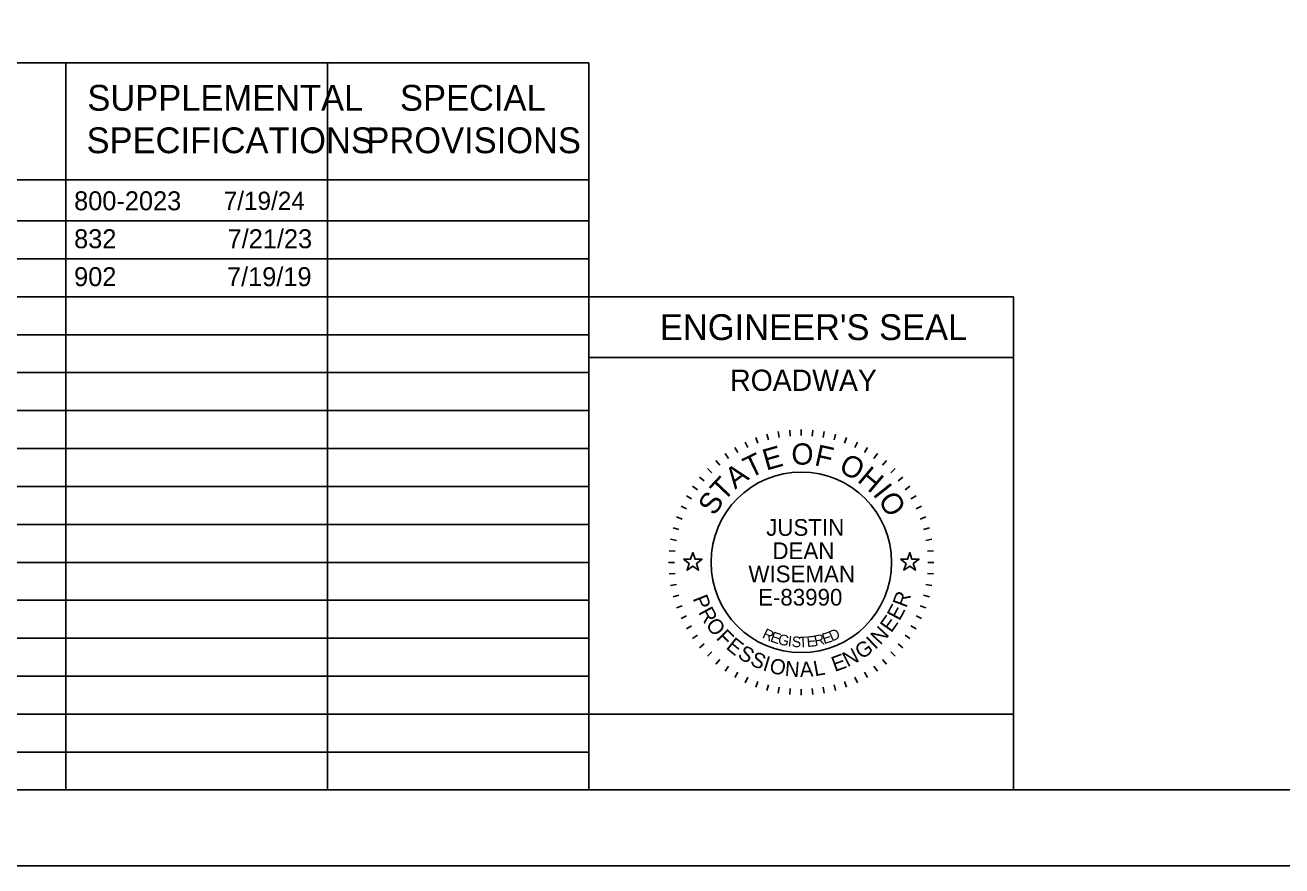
# Model space of a CAD drawing. Extents: x 0 to 34, y 0 to 22.
# Drawn here: x 19.88 to 28.17, y 0 to 5.54 of the extents above; entities that cross this region are included whole.
import ezdxf

# ---------------------------------------------------------------- set-up
doc = ezdxf.new("R2010")
doc.units = 0
for name, color, linetype in [('Default', 7, 'Continuous'), ('SH_Border', 7, 'Continuous'), ('SH_Cut_Line', 7, 'Continuous'), ('SH_Data', 7, 'Continuous'), ('SH_Text', 7, 'Continuous')]:
    doc.layers.add(name, color=color, linetype=linetype)

msp = doc.modelspace()

# ---------------------------------------------------------------- linework, layer by layer
at = {"layer": 'Default'}
for points in [[(24.2236, 2.02), (24.2705, 2.02), (24.285, 2.0645), (24.2995, 2.02), (24.3464, 2.02), (24.3085, 1.9924), (24.323, 1.9478), (24.285, 1.9754), (24.247, 1.9478), (24.2615, 1.9924)], [(25.6536, 2.02), (25.7005, 2.02), (25.715, 2.0645), (25.7295, 2.02), (25.7764, 2.02), (25.7385, 1.9924), (25.753, 1.9478), (25.715, 1.9754), (25.677, 1.9478), (25.6915, 1.9924)]]:
    msp.add_lwpolyline(points, close=True, dxfattribs=at)
at = {"layer": 'SH_Border'}
msp.add_lwpolyline([(1.5, 21.5), (33.5, 21.5), (33.5, 0.5), (1.5, 0.5)], close=True, dxfattribs=at)
at = {"layer": 'SH_Cut_Line'}
msp.add_lwpolyline([(0, 0), (34, 0), (34, 22), (0, 22)], close=True, dxfattribs=at)
at = {"layer": 'SH_Data'}
for p, q in [((10.15, 5.2917), (23.6, 5.2917)), ((20.15, 0.5), (20.15, 5.2917)), ((21.875, 0.5), (21.875, 5.2917)), ((23.6, 0.5), (23.6, 5.2917)), ((10.15, 4.5209), (23.6, 4.5209)), ((10.15, 4.25), (23.6, 4.25)), ((10.15, 4), (23.6, 4)), ((10.15, 3.75), (23.6, 3.75)), ((23.6, 0.5), (23.6, 3.75)), ((23.6, 3.75), (26.4, 3.75)), ((26.4, 3.75), (26.4, 0.5)), ((10.15, 3.5), (23.6, 3.5)), ((23.6, 3.35), (26.4, 3.35)), ((10.15, 3.25), (23.6, 3.25)), ((10.15, 3), (23.6, 3)), ((24.7007, 2.8222), (24.7144, 2.7846)), ((24.7735, 2.8452), (24.7839, 2.8065)), ((24.8481, 2.8617), (24.855, 2.8223)), ((24.9237, 2.8717), (24.9272, 2.8318)), ((25, 2.875), (25, 2.835)), ((25.0763, 2.8717), (25.0728, 2.8318)), ((25.1519, 2.8617), (25.145, 2.8223)), ((25.2265, 2.8452), (25.2161, 2.8065)), ((25.2993, 2.8222), (25.2856, 2.7846)), ((10.15, 2.75), (23.6, 2.75)), ((24.5625, 2.7578), (24.5825, 2.7231)), ((24.6302, 2.793), (24.6471, 2.7568)), ((25.3698, 2.793), (25.3529, 2.7568)), ((25.4375, 2.7578), (25.4175, 2.7231)), ((24.4376, 2.6703), (24.4633, 2.6396)), ((24.4981, 2.7168), (24.5211, 2.684)), ((25.5019, 2.7168), (25.4789, 2.684)), ((25.5624, 2.6703), (25.5367, 2.6396)), ((24.3813, 2.6187), (24.4096, 2.5904)), ((25.6187, 2.6187), (25.5904, 2.5904)), ((10.15, 2.5), (23.6, 2.5)), ((24.2832, 2.5019), (24.316, 2.4789)), ((24.3297, 2.5624), (24.3604, 2.5367)), ((25.6703, 2.5624), (25.6396, 2.5367)), ((25.7168, 2.5019), (25.684, 2.4789)), ((24.2422, 2.4375), (24.2769, 2.4175)), ((25.7578, 2.4375), (25.7231, 2.4175)), ((24.207, 2.3698), (24.2432, 2.3529)), ((25.793, 2.3698), (25.7568, 2.3529)), ((10.15, 2.25), (23.6, 2.25)), ((24.1778, 2.2993), (24.2154, 2.2856)), ((25.8222, 2.2993), (25.7846, 2.2856)), ((24.1548, 2.2265), (24.1935, 2.2161)), ((25.8452, 2.2265), (25.8065, 2.2161)), ((24.1283, 2.0763), (24.1682, 2.0728)), ((24.1383, 2.1519), (24.1777, 2.145)), ((25.8617, 2.1519), (25.8223, 2.145)), ((25.8717, 2.0763), (25.8318, 2.0728)), ((10.15, 2), (23.6, 2)), ((24.125, 2), (24.165, 2)), ((25.875, 2), (25.835, 2)), ((24.1283, 1.9237), (24.1682, 1.9272)), ((25.8717, 1.9237), (25.8318, 1.9272)), ((24.1383, 1.8481), (24.1777, 1.855)), ((25.8617, 1.8481), (25.8223, 1.855)), ((10.15, 1.75), (23.6, 1.75)), ((24.1548, 1.7735), (24.1935, 1.7839)), ((25.8452, 1.7735), (25.8065, 1.7839)), ((24.1778, 1.7007), (24.2154, 1.7144)), ((25.8222, 1.7007), (25.7846, 1.7144)), ((24.207, 1.6302), (24.2432, 1.6471)), ((24.2422, 1.5625), (24.2769, 1.5825)), ((25.7578, 1.5625), (25.7231, 1.5825)), ((25.793, 1.6302), (25.7568, 1.6471)), ((10.15, 1.5), (23.6, 1.5)), ((24.2832, 1.4981), (24.316, 1.5211)), ((25.7168, 1.4981), (25.684, 1.5211)), ((24.3297, 1.4376), (24.3604, 1.4633)), ((24.3813, 1.3813), (24.4096, 1.4096)), ((25.6187, 1.3813), (25.5904, 1.4096)), ((25.6703, 1.4376), (25.6396, 1.4633)), ((24.4376, 1.3297), (24.4633, 1.3604)), ((25.5624, 1.3297), (25.5367, 1.3604)), ((10.15, 1.25), (23.6, 1.25)), ((24.4981, 1.2832), (24.5211, 1.316)), ((24.5625, 1.2422), (24.5825, 1.2769)), ((24.6302, 1.207), (24.6471, 1.2432)), ((25.3698, 1.207), (25.3529, 1.2432)), ((25.4375, 1.2422), (25.4175, 1.2769)), ((25.5019, 1.2832), (25.4789, 1.316)), ((24.7007, 1.1778), (24.7144, 1.2154)), ((24.7735, 1.1548), (24.7839, 1.1935)), ((24.8481, 1.1383), (24.855, 1.1777)), ((24.9237, 1.1283), (24.9272, 1.1682)), ((25, 1.125), (25, 1.165)), ((25.0763, 1.1283), (25.0728, 1.1682)), ((25.1519, 1.1383), (25.145, 1.1777)), ((25.2265, 1.1548), (25.2161, 1.1935)), ((25.2993, 1.1778), (25.2856, 1.2154)), ((10.15, 1), (23.6, 1)), ((10.15, 0.75), (23.6, 0.75)), ((23.6, 0.5), (26.4, 0.5))]:
    msp.add_line(p, q, dxfattribs=at)
msp.add_lwpolyline([(23.6, 0.5), (23.6, 1), (26.4, 1), (26.4, 0.5)], close=True, dxfattribs=at)
msp.add_circle((25, 2), 0.595, dxfattribs=at)

# ---------------------------------------------------------------- texts
for s, height, p in [("ENGINEER'S SEAL", 0.17, (24.0676, 3.465)), ('ROADWAY', 0.14, (24.5311, 3.13)), ('JUSTIN', 0.11, (24.7686, 2.1749)), ('DEAN', 0.11, (24.8097, 2.0216)), ('WISEMAN', 0.11, (24.6516, 1.8684)), ('E-83990', 0.11, (24.7149, 1.7151))]:
    msp.add_text(s, height=height, dxfattribs=at).set_placement(p)
for s, height, rotation, p in [('E', 0.14, 15.75706, (24.7684, 2.6038)), ('O', 0.14, 359.78119, (24.9347, 2.6443)), ('F', 0.14, 347.43619, (25.0811, 2.6417)), ('T', 0.14, 25.71674, (24.6616, 2.5518)), ('O', 0.14, 332.25863, (25.2398, 2.6015)), ('T', 0.14, 46.4344, (24.4883, 2.3964)), ('A', 0.14, 36.47472, (24.5634, 2.4781)), ('H', 0.14, 319.91363, (25.3632, 2.5361)), ('I', 0.14, 308.36695, (25.4665, 2.4483)), ('S', 0.14, 57.19238, (24.4281, 2.3014)), ('O', 0.14, 303.14906, (25.5021, 2.4089)), ('P', 0.1, 291.49398, (24.2823, 1.7621)), ('R', 0.1, 69.23216, (25.6919, 1.6954)), ('R', 0.1, 298.73106, (24.319, 1.6717)), ('E', 0.1, 61.99508, (25.6476, 1.6098)), ('O', 0.1, 306.46664, (24.3655, 1.5883)), ('N', 0.1, 47.02243, (25.5202, 1.4508)), ('E', 0.1, 54.75801, (25.5933, 1.5314)), ('F', 0.1, 314.7068, (24.4343, 1.4983)), ('E', 0.1, 321.43929, (24.4978, 1.4348)), ('R', 0.07, 334.48695, (24.7375, 1.5051)), ('E', 0.07, 341.03996, (24.7906, 1.4801)), ('G', 0.07, 347.47515, (24.8414, 1.4618)), ('I', 0.07, 353.78581, (24.9091, 1.4468)), ('S', 0.07, 356.89262, (24.9358, 1.4429)), ('T', 0.07, 3.00609, (24.9857, 1.4387)), ('E', 0.07, 6.01169, (25.0389, 1.4412)), ('R', 0.07, 11.91844, (25.0925, 1.4474)), ('E', 0.07, 17.68363, (25.1498, 1.4602)), ('D', 0.07, 23.30524, (25.201, 1.477)), ('I', 0.1, 43.28703, (25.4868, 1.4214)), ('S', 0.1, 328.67637, (24.5743, 1.3752)), ('N', 0.1, 27.31129, (25.3045, 1.3075)), ('G', 0.1, 35.04687, (25.3981, 1.357)), ('S', 0.1, 335.91345, (24.6564, 1.3266)), ('I', 0.1, 343.15053, (24.7406, 1.2897)), ('O', 0.1, 346.88592, (24.7839, 1.2751)), ('N', 0.1, 355.12608, (24.8888, 1.2517)), ('A', 0.1, 2.86166, (24.9923, 1.2437)), ('L', 0.1, 10.09874, (25.0894, 1.249)), ('E', 0.1, 20.07421, (25.2212, 1.277))]:
    msp.add_text(s, height=height, rotation=rotation, dxfattribs=at).set_placement(p)
at = {"layer": 'SH_Text'}
for s, height, p in [('SUPPLEMENTAL', 0.17, (20.2925, 4.9763)), ('SPECIAL', 0.17, (22.3542, 4.9763)), ('SPECIFICATIONS', 0.17, (20.2871, 4.6963)), ('PROVISIONS', 0.17, (22.1323, 4.6963)), ('800-2023', 0.125, (20.205, 4.32)), ('7/19/24', 0.12, (21.1913, 4.3225)), ('832', 0.125, (20.205, 4.07)), ('7/21/23', 0.125, (21.2171, 4.07)), ('902', 0.125, (20.205, 3.82)), ('7/19/19', 0.125, (21.2132, 3.82))]:
    msp.add_text(s, height=height, dxfattribs=at).set_placement(p)

doc.saveas('drawing.dxf')
